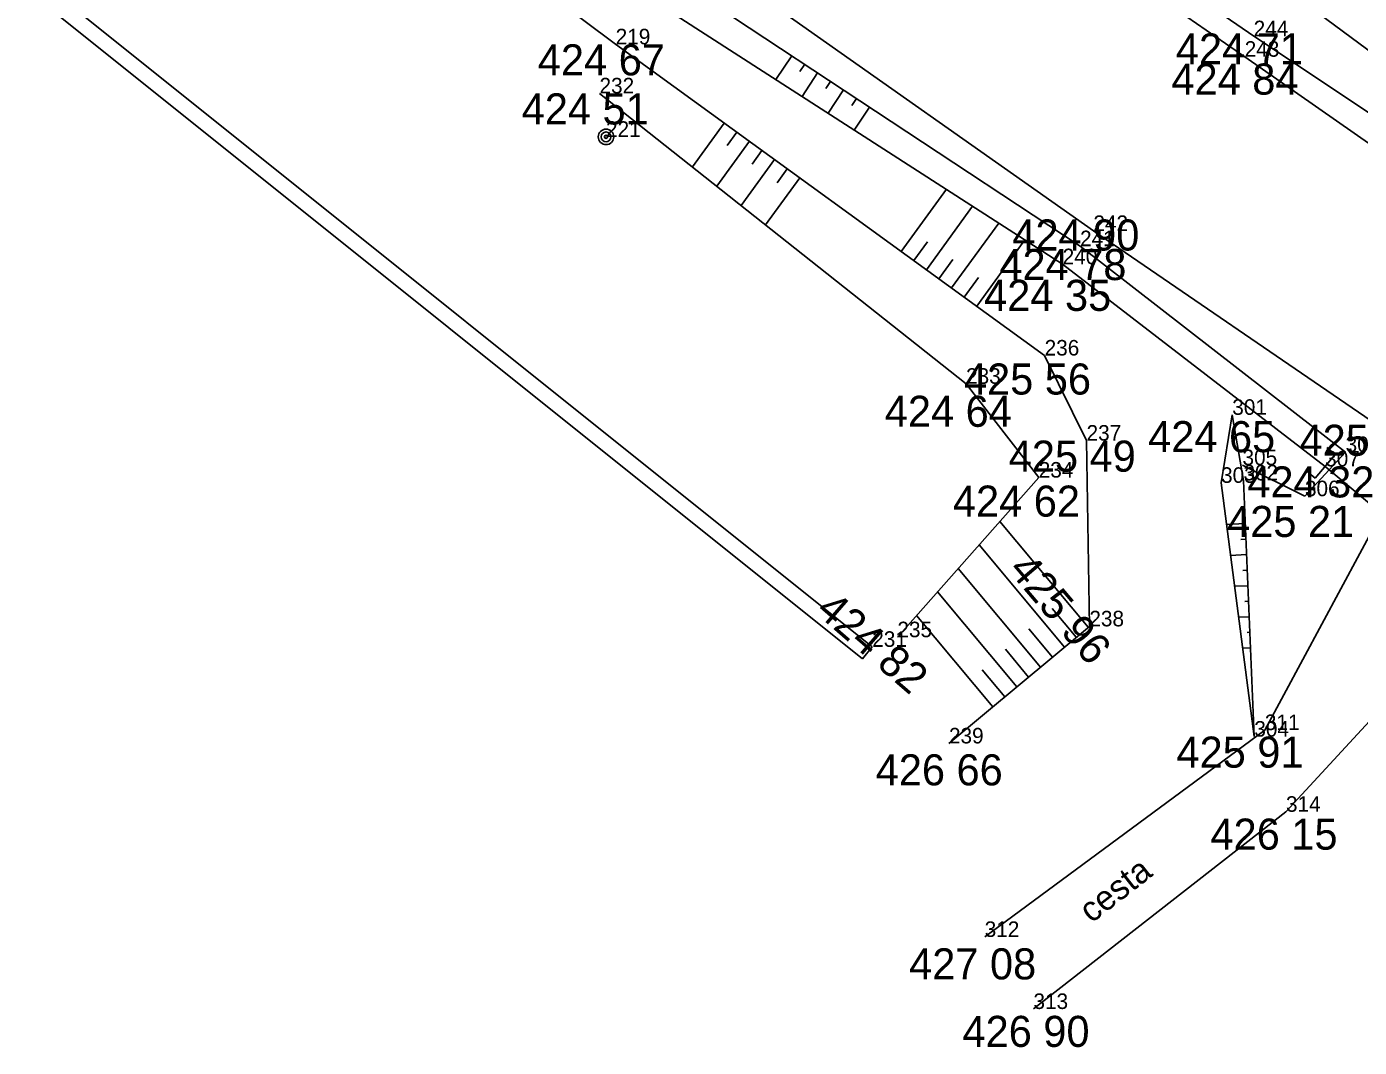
# Model space of a CAD drawing. Extents: x -559180 to -551373, y -1076947 to -1072071.
# Drawn here: x -554530.75 to -554487.85, y -1073711.27 to -1073678.4 of the extents above; entities that cross this region are included whole.
import ezdxf

# ---------------------------------------------------------------- set-up
doc = ezdxf.new("R2010")
doc.units = 0
for name, color, linetype in [('12_PLOTY', 7, 'Continuous'), ('17_KOMUNIKACE', 7, 'Continuous'), ('1_VODA_ZN', 7, 'Continuous'), ('20_EL_ZN', 7, 'Continuous'), ('26_SRAFY', 7, 'Continuous'), ('27_HRANA_PATA', 7, 'Continuous'), ('3_BODY', 7, 'Continuous'), ('40_KANAL_ZN', 7, 'Continuous'), ('52_POPIS_UCELOVY', 7, 'Continuous'), ('6_VYSKY', 7, 'Continuous')]:
    doc.layers.add(name, color=color, linetype=linetype)

# ---------------------------------------------------------------- blocks, each defined once
blk = doc.blocks.new('SLB')
at = {"layer": '20_EL_ZN'}
for radius in [0.25, 0.158, 0.05]:
    blk.add_circle((0, 0), radius, dxfattribs=at)
blk = doc.blocks.new('VYUST')
at = {"layer": '40_KANAL_ZN'}
for p, q in [((-0.35, 0.5), (0, 0.5)), ((0, 0.5), (0, -0.5)), ((0, 0), (3, 0.001)), ((-0.35, -0.5), (0, -0.5))]:
    blk.add_line(p, q, dxfattribs=at)
blk = doc.blocks.new('POINT_DISPLAY')
blk.add_line((0, 0), (0, 0))

msp = doc.modelspace()

# ---------------------------------------------------------------- linework, layer by layer
at = {"layer": '12_PLOTY'}
for p, q in [((-554530.752, -1073677.22), (-554503.842, -1073698.76)), ((-554503.53, -1073698.37), (-554530.44, -1073676.83)), ((-554503.842, -1073698.76), (-554503.53, -1073698.37))]:
    msp.add_line(p, q, dxfattribs=at)
at = {"layer": '17_KOMUNIKACE'}
for p, q in [((-554505.63, -1073669.64), (-554491.54, -1073679.37)), ((-554510.21, -1073675.25), (-554496.41, -1073684.98)), ((-554491.54, -1073679.37), (-554483.56, -1073684.95)), ((-554496.41, -1073684.98), (-554487.47, -1073691.09)), ((-554487.22, -1073694.23), (-554490.89, -1073701.05)), ((-554490.21, -1073703.68), (-554483.5, -1073696.38)), ((-554490.89, -1073701.05), (-554499.91, -1073707.71)), ((-554498.34, -1073710.03), (-554490.21, -1073703.68))]:
    msp.add_line(p, q, dxfattribs=at)
at = {"layer": '26_SRAFY'}
for p, q in [((-554506.629, -1073680.107), (-554506.122, -1073679.338)), ((-554505.856, -1073679.843), (-554505.704, -1073679.614)), ((-554505.789, -1073680.648), (-554505.287, -1073679.889)), ((-554505.02, -1073680.391), (-554504.87, -1073680.165)), ((-554504.948, -1073681.19), (-554504.453, -1073680.44)), ((-554504.183, -1073680.939), (-554504.036, -1073680.716)), ((-554504.107, -1073681.731), (-554503.619, -1073680.992)), ((-554509.319, -1073682.92), (-554508.294, -1073681.507)), ((-554508.2, -1073682.23), (-554507.889, -1073681.8)), ((-554508.535, -1073683.542), (-554507.484, -1073682.094)), ((-554507.75, -1073684.163), (-554506.675, -1073682.681)), ((-554507.398, -1073682.827), (-554507.08, -1073682.388)), ((-554506.596, -1073683.425), (-554506.27, -1073682.975)), ((-554506.966, -1073684.785), (-554505.865, -1073683.269)), ((-554501.143, -1073683.639), (-554502.596, -1073685.641)), ((-554500.301, -1073684.182), (-554501.786, -1073686.228)), ((-554499.459, -1073684.724), (-554500.977, -1073686.816)), ((-554501.75, -1073685.327), (-554502.191, -1073685.935)), ((-554498.617, -1073685.266), (-554500.167, -1073687.403)), ((-554500.931, -1073685.901), (-554501.382, -1073686.522)), ((-554500.112, -1073686.475), (-554500.572, -1073687.109)), ((-554499.42, -1073694.332), (-554496.576, -1073697.74)), ((-554492.125, -1073694.429), (-554491.521, -1073694.403)), ((-554500.09, -1073695.089), (-554497.344, -1073698.381)), ((-554491.668, -1073694.91), (-554491.5, -1073694.903)), ((-554491.995, -1073695.424), (-554491.479, -1073695.402)), ((-554500.76, -1073695.846), (-554498.112, -1073699.021)), ((-554491.599, -1073695.908), (-554491.457, -1073695.902)), ((-554491.864, -1073696.42), (-554491.436, -1073696.402)), ((-554501.431, -1073696.604), (-554498.88, -1073699.662)), ((-554491.53, -1073696.906), (-554491.415, -1073696.901)), ((-554502.101, -1073697.361), (-554499.648, -1073700.302)), ((-554497.735, -1073697.132), (-554496.96, -1073698.061)), ((-554491.734, -1073697.415), (-554491.394, -1073697.401)), ((-554498.488, -1073697.79), (-554497.728, -1073698.701)), ((-554491.461, -1073697.904), (-554491.373, -1073697.9)), ((-554499.241, -1073698.448), (-554498.496, -1073699.342)), ((-554491.603, -1073698.41), (-554491.351, -1073698.4)), ((-554499.994, -1073699.107), (-554499.264, -1073699.982))]:
    msp.add_line(p, q, dxfattribs=at)
at = {"layer": '27_HRANA_PATA'}
for p, q in [((-554529.54, -1073665.66), (-554511.79, -1073678.97)), ((-554505.19, -1073669.05), (-554491.25, -1073678.71)), ((-554492.01, -1073675.85), (-554482.51, -1073682.92)), ((-554510.72, -1073676.3), (-554496.84, -1073685.47)), ((-554511.05, -1073677.26), (-554497.4, -1073686.05)), ((-554491.25, -1073678.71), (-554482.88, -1073684.28)), ((-554511.79, -1073678.97), (-554497.98, -1073688.99)), ((-554512.31, -1073680.55), (-554500.51, -1073689.9)), ((-554496.84, -1073685.47), (-554488.29, -1073692.1)), ((-554497.4, -1073686.05), (-554488.95, -1073692.56)), ((-554497.98, -1073688.99), (-554496.63, -1073691.73)), ((-554500.51, -1073689.9), (-554498.17, -1073692.92)), ((-554491.94, -1073690.9), (-554492.3, -1073693.09)), ((-554491.94, -1073690.9), (-554491.58, -1073693.01)), ((-554496.63, -1073691.73), (-554496.54, -1073697.71)), ((-554489.6, -1073693.52), (-554488.29, -1073692.1)), ((-554491.61, -1073692.52), (-554489.6, -1073693.52)), ((-554498.17, -1073692.92), (-554502.72, -1073698.06)), ((-554492.3, -1073693.09), (-554491.23, -1073701.26)), ((-554491.58, -1073693.01), (-554491.23, -1073701.26)), ((-554496.54, -1073697.71), (-554501.06, -1073701.48))]:
    msp.add_line(p, q, dxfattribs=at)

# ---------------------------------------------------------------- block references
at = {"layer": '1_VODA_ZN'}
for p in [(-554491.25, -1073678.71), (-554511.79, -1073678.97), (-554491.54, -1073679.37), (-554512.31, -1073680.55), (-554512.1, -1073681.95), (-554496.41, -1073684.98), (-554496.84, -1073685.47), (-554497.4, -1073686.05), (-554497.98, -1073688.99), (-554500.51, -1073689.9), (-554491.94, -1073690.9), (-554496.63, -1073691.73), (-554488.29, -1073692.1), (-554491.61, -1073692.52), (-554488.95, -1073692.56), (-554498.17, -1073692.92), (-554492.3, -1073693.09), (-554491.58, -1073693.01), (-554489.6, -1073693.52), (-554496.54, -1073697.71), (-554502.72, -1073698.06), (-554503.53, -1073698.37), (-554491.23, -1073701.26), (-554490.89, -1073701.05), (-554501.06, -1073701.48), (-554490.21, -1073703.68), (-554499.91, -1073707.71), (-554498.34, -1073710.03)]:
    msp.add_blockref('POINT_DISPLAY', p, dxfattribs=at)
at = {"layer": '20_EL_ZN'}
msp.add_blockref('SLB', (-554512.1, -1073681.95), dxfattribs=at)
at = {"layer": '40_KANAL_ZN', "xscale": 1.000001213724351, "yscale": 1.000001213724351, "rotation": -39.90514988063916}
msp.add_blockref('VYUST', (-554488.95, -1073692.56), dxfattribs=at)

# ---------------------------------------------------------------- texts
at = {"layer": '3_BODY'}
for s, p in [('219', (-554511.79, -1073678.97)), ('244', (-554491.25, -1073678.71)), ('243', (-554491.54, -1073679.37)), ('232', (-554512.31, -1073680.55)), ('221', (-554512.1, -1073681.95)), ('242', (-554496.41, -1073684.98)), ('241', (-554496.84, -1073685.47)), ('240', (-554497.4, -1073686.05)), ('236', (-554497.98, -1073688.99)), ('233', (-554500.51, -1073689.9)), ('301', (-554491.94, -1073690.9)), ('237', (-554496.63, -1073691.73)), ('308', (-554488.29, -1073692.1)), ('305', (-554491.61, -1073692.52)), ('307', (-554488.95, -1073692.56)), ('234', (-554498.17, -1073692.92)), ('303', (-554492.3, -1073693.09)), ('302', (-554491.58, -1073693.01)), ('306', (-554489.6, -1073693.52)), ('238', (-554496.54, -1073697.71)), ('235', (-554502.72, -1073698.06)), ('231', (-554503.53, -1073698.37)), ('304', (-554491.23, -1073701.26)), ('311', (-554490.89, -1073701.05)), ('239', (-554501.06, -1073701.48)), ('314', (-554490.21, -1073703.68)), ('312', (-554499.91, -1073707.71)), ('313', (-554498.34, -1073710.03))]:
    msp.add_text(s, height=0.5, dxfattribs=at).set_placement(p)
at = {"layer": '52_POPIS_UCELOVY'}
msp.add_text('cesta', height=0.8, rotation=37.9919, dxfattribs=at).set_placement((-554496.474, -1073707.289))
at = {"layer": '6_VYSKY'}
for s, p in [('424 71', (-554493.755, -1073679.618)), ('424 67', (-554514.295, -1073679.97)), ('424 84', (-554493.898, -1073680.59)), ('424 51', (-554514.815, -1073681.55)), ('424 90', (-554499.021, -1073685.61)), ('424 78', (-554499.437, -1073686.562)), ('424 35', (-554499.927, -1073687.553)), ('425 56', (-554500.577, -1073690.247)), ('424 64', (-554503.126, -1073691.286)), ('424 65', (-554494.648, -1073692.102)), ('425 09', (-554489.773, -1073692.219)), ('425 49', (-554499.135, -1073692.73)), ('424 32', (-554491.455, -1073693.56)), ('424 62', (-554500.932, -1073694.178)), ('425 21', (-554492.105, -1073694.832)), ('425 91', (-554493.735, -1073702.26)), ('426 66', (-554503.418, -1073702.83)), ('426 15', (-554492.641, -1073704.9)), ('427 08', (-554502.342, -1073709.077)), ('426 90', (-554500.624, -1073711.251))]:
    msp.add_text(s, height=1, dxfattribs=at).set_placement(p)
for s, rotation, p in [('425 96', 310.3792, (-554499.179, -1073695.905)), ('424 82', 319.1089, (-554505.389, -1073697.27))]:
    msp.add_text(s, height=1, rotation=rotation, dxfattribs=at).set_placement(p)

doc.saveas('drawing.dxf')
